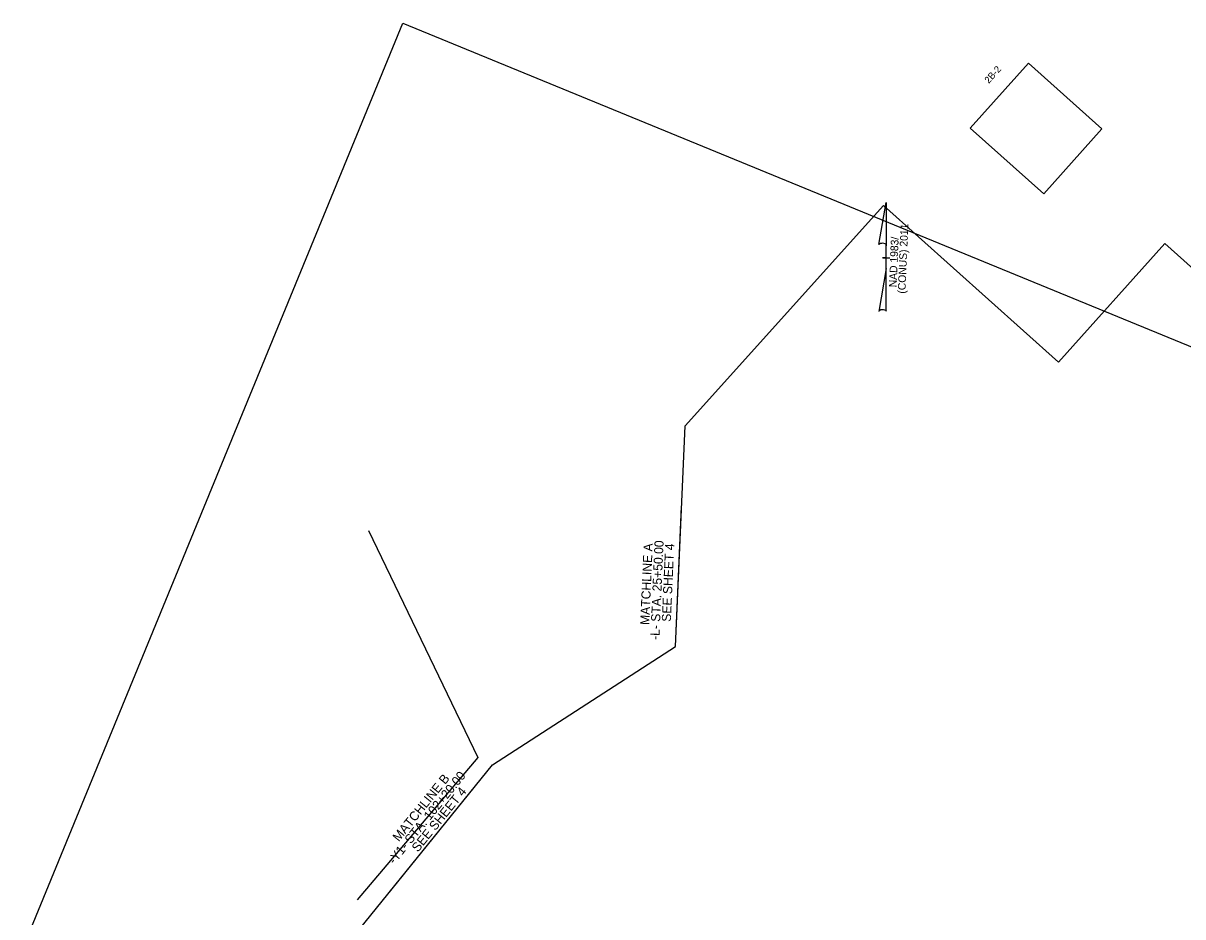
# Model space of a CAD drawing. Extents: x 2090929 to 2092919, y 862732 to 864596.
# Drawn here: x 2090929 to 2092205, y 863612 to 864596 of the extents above; entities that cross this region are included whole.
import ezdxf

# ---------------------------------------------------------------- set-up
doc = ezdxf.new("R2010")
doc.units = 0
for name, color, linetype in [('Matchline', 7, 'Continuous'), ('Matchline Text', 7, 'Continuous'), ('Prop North Arrow for Plan Sheets CELL', 7, 'Continuous'), ('Prop North Arrow NAD83 for Plan Sheets CELL', 7, 'Continuous'), ('Scratch_Level_6', 7, 'Continuous'), ('Scratch_Level_7', 7, 'Continuous'), ('Sheet Clip Boundary CELL', 7, 'Continuous'), ('Sheet Data Field CELL', 7, 'Continuous')]:
    doc.layers.add(name, color=color, linetype=linetype)

msp = doc.modelspace()

# ---------------------------------------------------------------- linework, layer by layer
at = {"layer": 'Matchline'}
for p, q in [((2091646.7, 863909.8), (2091653.5, 864064)), ((2091328.8, 863635.3), (2091445.4, 863779.5))]:
    msp.add_line(p, q, dxfattribs=at)
at = {"layer": 'Prop North Arrow for Plan Sheets CELL'}
for p, q in [((2091870.5, 864352.1), (2091878.7, 864398.4)), ((2091878.8, 864398.4), (2091878.7, 864398.4)), ((2091878.8, 864398.4), (2091878.7, 864398.4)), ((2091878.8, 864398.4), (2091878.8, 864350.6)), ((2091878.8, 864325.8), (2091878.8, 864352)), ((2091878.8, 864350.6), (2091878.8, 864352)), ((2091874.8, 864337.4), (2091874.7, 864337.4)), ((2091874.8, 864337.4), (2091882.8, 864337.4)), ((2091878.3, 864337.4), (2091874.8, 864337.4)), ((2091878.8, 864325.8), (2091870.4, 864278.6)), ((2091878.8, 864278.8), (2091878.8, 864325.8))]:
    msp.add_line(p, q, dxfattribs=at)
for centre, start_param, end_param in [((2091874.7, 864351.6), 0.216388, 2.908219), ((2091874.7, 864278.4), 0.201328, 3.141593)]:
    msp.add_ellipse(centre, major_axis=(4.23, -0.03), ratio=0.461098, start_param=start_param, end_param=end_param, dxfattribs=at)
at = {"layer": 'Scratch_Level_6'}
for p, q in [((2091309, 864037.4), (2091429.5, 863787.6)), ((2091429.5, 863787.6), (2091296.4, 863630.9))]:
    msp.add_line(p, q, dxfattribs=at)
msp.add_lwpolyline([(2091346.9, 864595.8), (2092919.5, 863950), (2092501.6, 862932.5), (2090929.1, 863578.3)], close=True, dxfattribs=at)
at = {"layer": 'Scratch_Level_7'}
msp.add_lwpolyline([(2091971.2, 864480.3), (2092035.2, 864551.8), (2092116.1, 864479.4), (2092052, 864407.9)], close=True, dxfattribs=at)
at = {"layer": 'Sheet Clip Boundary CELL'}
msp.add_lwpolyline([(2091803.8, 862815.7), (2091354.2, 863218.1), (2091094.6, 863450.5), (2091157.4, 863520.8), (2091216.6, 863496.5), (2091445.4, 863779.5), (2091646.7, 863909.8), (2091657.4, 864152.6), (2091875.6, 864395.3), (2092068.4, 864222.8), (2092185.2, 864353.2), (2092693.1, 863898.6), (2092566.8, 863757.5), (2092611.2, 863717.7)], close=True, dxfattribs=at)
msp.add_lwpolyline([(2091875.6, 864395.3), (2092068.4, 864222.8), (2092185.2, 864353.2)], dxfattribs=at)

# ---------------------------------------------------------------- texts
at = {"layer": 'Matchline Text'}
for s, rotation, p in [('MATCHLINE A', 87.4725, (2091617.9, 863933.3)), ('-L- STA. 25+50.00', 87.4725, (2091629, 863916.8)), ('SEE SHEET 4', 87.4725, (2091641.7, 863936.8)), ('-Y1- STA. 102+20.00 ', 51.0406, (2091337.4, 863669.3)), ('MATCHLINE B', 51.0406, (2091342.4, 863694.3)), ('SEE SHEET 4', 51.0406, (2091363.4, 863682.8))]:
    msp.add_text(s, height=10, rotation=rotation, dxfattribs=at).set_placement(p)
at = {"layer": 'Prop North Arrow NAD83 for Plan Sheets CELL'}
for s, p in [('(CONUS) 2011', (2091899.8, 864298)), ('NAD 1983/ ', (2091890.1, 864305))]:
    msp.add_text(s, height=8.5, rotation=87.5603, dxfattribs=at).set_placement(p)
at = {"layer": 'Sheet Data Field CELL'}
msp.add_text('2B-2', height=7.5, rotation=48.1706, dxfattribs=at).set_placement((2091991.6, 864528.9))

doc.saveas('drawing.dxf')
